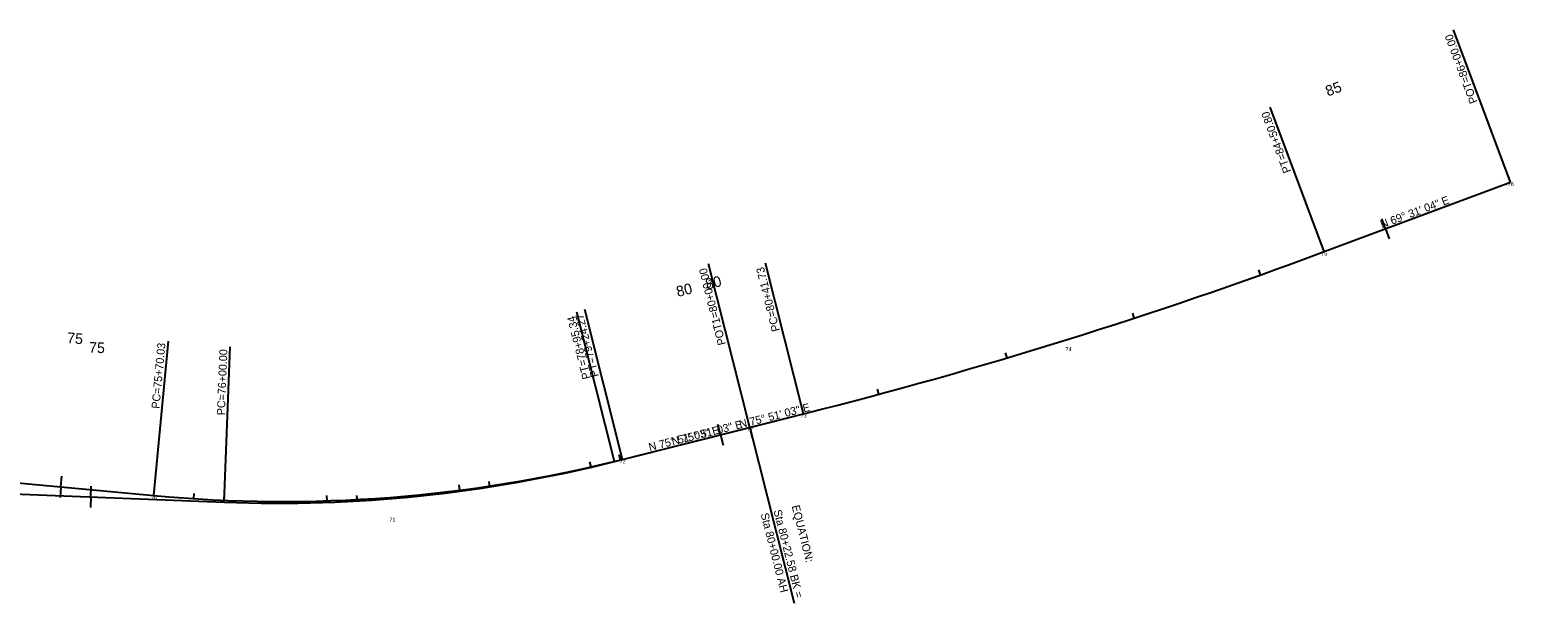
# Model space of a CAD drawing. Extents: x 1965771 to 1970246, y 1117124 to 1118239.
# Drawn here: x 1969133 to 1970246, y 1117809 to 1118239 of the extents above; entities that cross this region are included whole.
import ezdxf

# ---------------------------------------------------------------- set-up
doc = ezdxf.new("R2010")
doc.units = 0
for name, color, linetype in [('RD_HC_Cl', 7, 'Continuous'), ('RD_HC_Data', 7, 'Continuous'), ('RD_HC_Data_Tic', 7, 'Continuous'), ('RD_HC_Points', 7, 'Continuous'), ('RD_HC_TX_Sta50', 7, 'Continuous')]:
    doc.layers.add(name, color=color, linetype=linetype)

msp = doc.modelspace()

# ---------------------------------------------------------------- linework, layer by layer
at = {"layer": 'RD_HC_Cl'}
for p, q in [((1970104, 1118072.9), (1970243.8, 1118125.1)), ((1970104, 1118072.9), (1970243.8, 1118125.1)), ((1968277.4, 1117978.5), (1969226.4, 1117889.9)), ((1969571.8, 1117915.4), (1969713.7, 1117951.2)), ((1969673.3, 1117941), (1969713.7, 1117951.2)), ((1969577.9, 1117916.9), (1969673.3, 1117941)), ((1968120.3, 1117930.9), (1969279, 1117884.9))]:
    msp.add_line(p, q, dxfattribs=at)
for centre, radius, start, end in [((1968809, 1121539.8), 3700.9, 284.1493, 290.4823), ((1968809, 1121539.8), 3700.9, 284.1493, 290.4823), ((1969323.3, 1118927.1), 1041.7, 264.6661, 284.1493), ((1969319.9, 1118914.5), 1030.4, 267.7266, 284.1493)]:
    msp.add_arc(centre, radius, start, end, dxfattribs=at)
at = {"layer": 'RD_HC_Data'}
for p, q in [((1970243.8, 1118125.1), (1970201.1, 1118239.4)), ((1970243.8, 1118125.1), (1970201.1, 1118239.4)), ((1970104, 1118072.9), (1970063.6, 1118181.3)), ((1970104, 1118072.9), (1970063.6, 1118181.3)), ((1969673.3, 1117941), (1969642.3, 1118063.6)), ((1969713.7, 1117951.2), (1969685.2, 1118064.1)), ((1969713.7, 1117951.2), (1969685.2, 1118064.1)), ((1969571.8, 1117915.4), (1969543.5, 1118027.5)), ((1969577.9, 1117916.9), (1969549.6, 1118029.4)), ((1969226.4, 1117889.9), (1969237.3, 1118005.8)), ((1969279, 1117884.9), (1969283.6, 1118001.5)), ((1969673.3, 1117941), (1969706.5, 1117809))]:
    msp.add_line(p, q, dxfattribs=at)
at = {"layer": 'RD_HC_Data_Tic'}
for p, q in [((1970150.1, 1118090.1), (1970147.3, 1118097.6)), ((1970150.1, 1118090.1), (1970147.3, 1118097.6)), ((1970150.1, 1118090.1), (1970152.9, 1118082.6)), ((1970150.1, 1118090.1), (1970152.9, 1118082.6)), ((1970056.3, 1118055.4), (1970055, 1118059.2)), ((1970056.3, 1118055.4), (1970055, 1118059.2)), ((1969961.7, 1118023), (1969960.5, 1118026.8)), ((1969961.7, 1118023), (1969960.5, 1118026.8)), ((1969866.3, 1117993.1), (1969865.2, 1117997)), ((1969866.3, 1117993.1), (1969865.2, 1117997)), ((1969770.1, 1117965.9), (1969769.1, 1117969.7)), ((1969770.1, 1117965.9), (1969769.1, 1117969.7)), ((1969651.4, 1117935.5), (1969649.4, 1117943.2)), ((1969673.3, 1117941), (1969671.3, 1117948.7)), ((1969673.3, 1117941), (1969671.3, 1117948.7)), ((1969651.4, 1117935.5), (1969653.3, 1117927.7)), ((1969673.3, 1117941), (1969675.2, 1117933.2)), ((1969673.3, 1117941), (1969675.2, 1117933.2)), ((1969576.3, 1117916.5), (1969575.3, 1117920.4)), ((1969554.3, 1117911.3), (1969553.4, 1117915.2)), ((1969156.7, 1117896.4), (1969157.4, 1117904.3)), ((1969455.9, 1117893.8), (1969455.4, 1117897.8)), ((1969478.4, 1117896.4), (1969477.8, 1117900.3)), ((1969156.7, 1117896.4), (1969156, 1117888.4)), ((1969179.1, 1117888.9), (1969178.8, 1117880.9)), ((1969179.1, 1117888.9), (1969179.4, 1117896.9)), ((1969256.3, 1117887.5), (1969256.6, 1117891.5)), ((1969279, 1117884.9), (1969279.2, 1117888.9)), ((1969356.3, 1117885.9), (1969356.1, 1117889.9)), ((1969379, 1117885.8), (1969378.7, 1117889.8))]:
    msp.add_line(p, q, dxfattribs=at)

# ---------------------------------------------------------------- texts
at = {"layer": 'RD_HC_Data'}
for s, rotation, p in [('POT=86+00.00', 110.4823, (1970219.2, 1118185.3)), ('POT=86+00.00', 110.4823, (1970219.2, 1118185.3)), ('PT=84+50.80', 110.4823, (1970079.4, 1118133.1)), ('PT=84+50.80', 110.4823, (1970079.4, 1118133.1)), ('N 69%%d 31\' 04" E', 20.4823, (1970147.5, 1118090.2)), ('N 69%%d 31\' 04" E', 20.4823, (1970147.5, 1118090.2)), ('POT1=80+00.00', 104.1493, (1969655.4, 1118003.5)), ('PC=80+41.73', 104.1493, (1969695.9, 1118013.7)), ('PC=80+41.73', 104.1493, (1969695.9, 1118013.7)), ('PT=78+95.34', 104.1493, (1969553.9, 1117977.9)), ('PT=79+24.27', 104.1493, (1969560.1, 1117979.5)), ('PC=75+70.03', 84.6661, (1969230.5, 1117954.8)), ('PC=76+00.00', 87.7266, (1969279.6, 1117950)), ('N 75%%d 51\' 03" E', 14.1493, (1969666.2, 1117940.2)), ('N 75%%d 51\' 03" E', 14.1493, (1969598.3, 1117923.1)), ('N 75%%d 51\' 03" E', 14.1493, (1969615.5, 1117927.4)), ('Sta 80+00.00 AH', 284.1493, (1969681.4, 1117876)), ('Sta 80+22.58 BK = ', 284.1493, (1969691.1, 1117878.4)), ('EQUATION:', 284.1493, (1969704.7, 1117881.9))]:
    msp.add_text(s, height=6, rotation=rotation, dxfattribs=at).set_placement(p)
at = {"layer": 'RD_HC_Points'}
for s, p in [('76', (1970241.7, 1118122.1)), ('75', (1970101.8, 1118069.9)), ('74', (1969910.1, 1117998.2)), ('73', (1969711.4, 1117948.2)), ('77', (1969671.2, 1117938)), ('72', (1969575.6, 1117913.9)), ('70', (1969224.3, 1117886.9)), ('71', (1969403, 1117870.2))]:
    msp.add_text(s, height=3, dxfattribs=at).set_placement(p)
at = {"layer": 'RD_HC_TX_Sta50'}
for s, rotation, p in [('85', 20.4823, (1970106.9, 1118189.2)), ('85', 20.4823, (1970106.9, 1118189.2)), ('80', 14.1493, (1969641.2, 1118044.3)), ('80', 14.1493, (1969641.2, 1118044.3)), ('80', 14.1493, (1969619.3, 1118038.8)), ('75', 354.6661, (1969161, 1118004.4)), ('75', 357.7266, (1969177.6, 1117997.1))]:
    msp.add_text(s, height=8, rotation=rotation, dxfattribs=at).set_placement(p)

doc.saveas('drawing.dxf')
